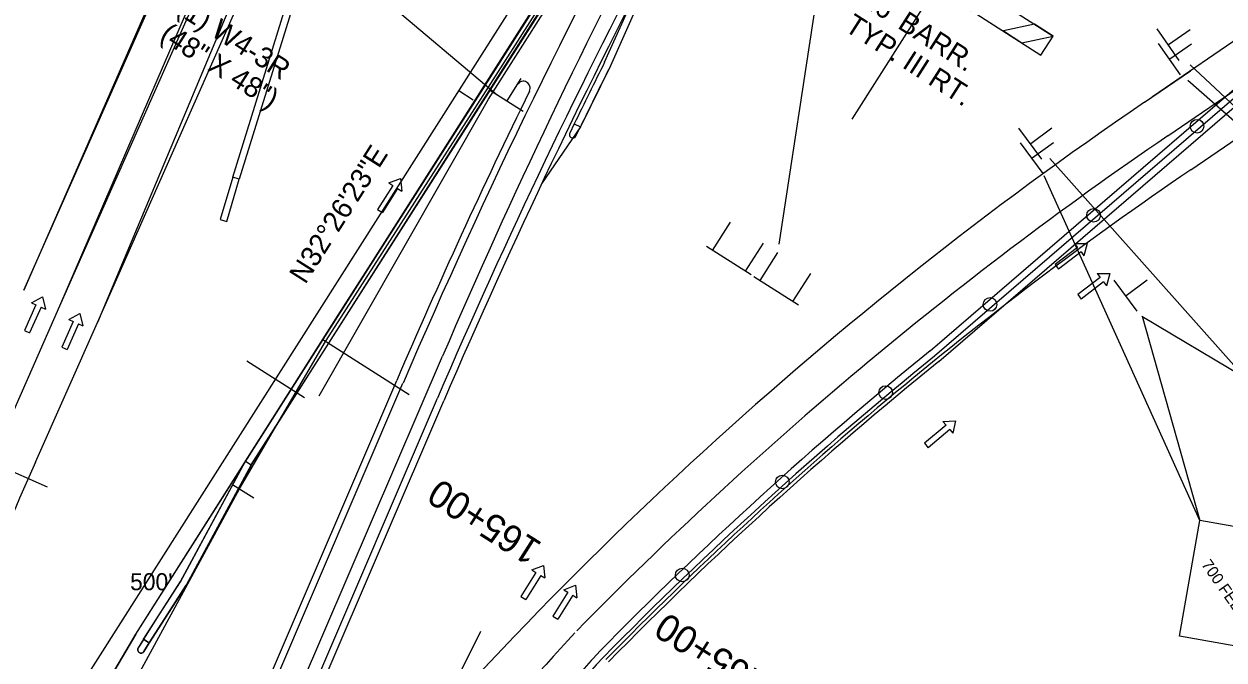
# Model space of a CAD drawing. Extents: x 659657 to 668193, y 633084 to 648639.
# Drawn here: x 661763.9 to 662115.3, y 641469.4 to 641655.6 of the extents above; entities that cross this region are included whole.
import ezdxf

# ---------------------------------------------------------------- set-up
doc = ezdxf.new("R2010")
doc.units = 0
for name, color, linetype in [('R_Draft', 7, 'Continuous'), ('R_MOT_Stage 1A', 7, 'Continuous'), ('R_MOT_Stage 1A_Striping', 7, 'Continuous'), ('R_MOT_Stage 1B', 7, 'Continuous'), ('R_MOT_Stage 1B_Striping', 7, 'Continuous'), ('R_MOT_Stage 1C', 7, 'Continuous'), ('R_MOT_Stage 1C_Striping', 7, 'Continuous'), ('R_MOT_Stage 2', 7, 'Continuous'), ('R_MOT_Stage 2_Striping', 7, 'Continuous'), ('R_MOT_Stage 2_Striping_PPM', 7, 'Continuous'), ('R_MOT_Stage 3_Striping_PPM', 7, 'Continuous'), ('R_MOT_Stage 4_Striping_PPM', 7, 'Continuous'), ('R_MOT_Stage 5_Striping_PPM', 7, 'Continuous'), ('R_ROW Annot', 7, 'Continuous'), ('S_EXISTING_ALIGNMENT', 7, 'Continuous'), ('T_Notes', 7, 'Continuous'), ('T_SIGNAL CONTROL CABINET', 7, 'Continuous'), ('TEMP_SIGNAL_HEAD_STAGE 2', 7, 'Continuous'), ('TEMP_SIGNAL_POLES_STAGE 3', 7, 'Continuous'), ('TEXT_TEMP_SIGNAL_POLES_STAGE 2', 7, 'Continuous')]:
    doc.layers.add(name, color=color, linetype=linetype)

msp = doc.modelspace()

# ---------------------------------------------------------------- linework, layer by layer
at = {"layer": 'R_Draft'}
for p, q in [((662102.51, 641640.73), (662096.07, 641649.95)), ((662099.44, 641645.41), (662105.74, 641649.81)), ((662200.7, 641554.26), (662104.7, 641639.1)), ((662062.3, 641611.81), (662055.63, 641620.87)), ((662059.12, 641616.41), (662065.3, 641620.96)), ((662108.18, 641510.21), (662062.63, 641611.16)), ((662089.81, 641571.52), (662083.14, 641580.58)), ((662086.62, 641576.13), (662092.81, 641580.68)), ((662091.31, 641570.11), (662108.18, 641510.21)), ((662102.25, 641476.33), (662108.18, 641510.21)), ((662142.04, 641504.27), (662108.18, 641510.21)), ((662136.13, 641470.4), (662102.25, 641476.33))]:
    msp.add_line(p, q, dxfattribs=at)
at = {"layer": 'R_MOT_Stage 1A'}
for p, q in [((661809.66, 641492.35), (661828.7, 641527.64)), ((661830.39, 641526.57), (661811.35, 641491.28)), ((661798.88, 641475.5), (661797.27, 641472.97)), ((661798.88, 641475.5), (661800.57, 641474.43)), ((661798.96, 641471.9), (661800.57, 641474.43))]:
    msp.add_line(p, q, dxfattribs=at)
for points in [[(661828.7, 641527.64), (661899.02, 641637.71), (661920.48, 641671.46), (661942.01, 641705.19), (661963.28, 641739.07), (661984.75, 641772.81), (662005.98, 641806.72), (662027.38, 641840.52), (662048.99, 641874.22)], [(661830.39, 641526.57), (661900.71, 641636.63), (661922.17, 641670.39), (661943.7, 641704.12), (661964.97, 641738), (661986.44, 641771.75), (662007.67, 641805.65), (662029.07, 641839.44), (662050.67, 641873.14)], [(661798.88, 641475.5), (661803.42, 641482.62), (661809.66, 641492.35)], [(661800.57, 641474.43), (661805.1, 641481.54), (661811.35, 641491.28)]]:
    msp.add_lwpolyline(points, dxfattribs=at)
msp.add_arc((661798.11, 641472.44), 1, 147.4916, 327.4916, dxfattribs=at)
at = {"layer": 'R_MOT_Stage 1A_Striping'}
for p, q in [((661764.81, 641437.19), (662110.96, 641981.8)), ((661853.01, 641388.39), (661897.69, 641477.85)), ((661771.17, 641433.87), (661796.6, 641476.95))]:
    msp.add_line(p, q, dxfattribs=at)
for points in [[(661796.6, 641476.95), (661855.9, 641570.33), (661877.49, 641604), (661899.02, 641637.71), (661920.48, 641671.46), (661942.01, 641705.19), (661963.28, 641739.07), (661984.75, 641772.81), (662005.98, 641806.72), (662027.38, 641840.52), (662048.99, 641874.22)], [(661895.42, 641633.35), (661891.2, 641636.03)], [(661829.12, 641557), (661845.99, 641546.27)]]:
    msp.add_lwpolyline(points, dxfattribs=at)
at = {"layer": 'R_MOT_Stage 1B'}
for p, q in [((661828.79, 641527.59), (662056.76, 641886.27)), ((661830.47, 641526.51), (662058.45, 641885.2)), ((661933.9, 641644.44), (661942.13, 641662.91)), ((661943.82, 641661.83), (661935.6, 641643.36)), ((661925.01, 641626.4), (661923.69, 641623.7)), ((661925.01, 641626.39), (661926.8, 641625.52)), ((661925.49, 641622.82), (661926.8, 641625.52)), ((661758.57, 641284.51), (661873.02, 641551.2)), ((661772.36, 641278.59), (661886.81, 641545.29)), ((661809.74, 641492.3), (661828.79, 641527.59)), ((661828.7, 641527.64), (661830.39, 641526.57)), ((661830.47, 641526.52), (661811.43, 641491.23)), ((661798.96, 641475.45), (661797.35, 641472.92)), ((661798.96, 641475.45), (661800.65, 641474.37)), ((661799.04, 641471.85), (661800.65, 641474.38))]:
    msp.add_line(p, q, dxfattribs=at)
for points in [[(661943.82, 641661.83), (661935.6, 641643.36), (661926.8, 641625.52), (661915.46, 641608.81)], [(661798.96, 641475.45), (661803.5, 641482.57), (661809.74, 641492.3)], [(661800.65, 641474.38), (661805.19, 641481.49), (661811.43, 641491.23)]]:
    msp.add_lwpolyline(points, dxfattribs=at)
for centre, radius, start, end in [((663629.94, 640797.24), 1896.86, 147.56037, 156.77389), ((663629.94, 640797.24), 1895.86, 153.4571, 154.06509), ((663629.94, 640797.24), 1893.86, 153.46335, 154.07199), ((663629.94, 640797.24), 1911.86, 153.97883, 156.77389), ((661910.08, 641636.86), 2, 333.9788, 147.532), ((661924.59, 641623.26), 1, 153.9653, 333.9653), ((661798.2, 641472.38), 1, 147.4916, 327.4916)]:
    msp.add_arc(centre, radius, start, end, dxfattribs=at)
at = {"layer": 'R_MOT_Stage 1B_Striping'}
for p, q in [((661764.81, 641437.19), (662110.96, 641981.8)), ((661796.6, 641476.95), (662056.76, 641886.27)), ((661760.41, 641283.72), (661874.86, 641550.41)), ((661770.52, 641279.38), (661884.97, 641546.08)), ((661796.6, 641476.95), (661771.17, 641433.87))]:
    msp.add_line(p, q, dxfattribs=at)
for points in [[(661895.42, 641633.35), (661891.2, 641636.03)], [(661829.12, 641557), (661845.99, 641546.27)]]:
    msp.add_lwpolyline(points, dxfattribs=at)
for radius, start in [(1898.86, 147.56037), (1909.86, 151.26731)]:
    msp.add_arc((663629.94, 640797.24), radius, start, 156.77389, dxfattribs=at)
at = {"layer": 'R_MOT_Stage 1C'}
for p, q in [((662029.22, 641559.88), (662143.21, 641658.04)), ((662144.43, 641656.46), (662030.5, 641558.35))]:
    msp.add_line(p, q, dxfattribs=at)
for centre in [(662107.37, 641625.7), (662077.06, 641599.6), (662046.75, 641573.5), (662016.19, 641547.71), (661985.93, 641521.51), (661956.61, 641494.26)]:
    msp.add_circle(centre, 2, dxfattribs=at)
for centre, radius, start, end in [((662748.35, 640671.56), 1142.92, 128.99148, 135.57268), ((662748.35, 640671.56), 1140.92, 128.98995, 135.57268), ((662771.33, 640697.15), 1141.93, 137.30278, 142.29975), ((662771.85, 640696.69), 1140.63, 137.30073, 142.29922)]:
    msp.add_arc(centre, radius, start, end, dxfattribs=at)
at = {"layer": 'R_MOT_Stage 1C_Striping'}
msp.add_line((662031.78, 641556.81), (662145.65, 641654.87), dxfattribs=at)
msp.add_arc((662748.35, 640671.56), 1138.92, 128.98842, 135.57268, dxfattribs=at)
at = {"layer": 'R_MOT_Stage 2'}
for points in [[(661825.01, 641610.82), (661878.63, 641783.81), (661880.54, 641783.21), (661826.92, 641610.23)], [(661825.01, 641610.82), (661821.37, 641598.34), (661823.29, 641597.78), (661826.92, 641610.23)]]:
    msp.add_lwpolyline(points, close=True, dxfattribs=at)
at = {"layer": 'R_MOT_Stage 2_Striping'}
for p, q in [((661803.9, 641669.37), (661763.88, 641577.73)), ((661774.4, 641573.08), (661813.96, 641664.92)), ((661824.02, 641660.47), (661785.37, 641568.22))]:
    msp.add_line(p, q, dxfattribs=at)
at = {"layer": 'R_MOT_Stage 2_Striping_PPM'}
for p, q in [((662474.17, 641893.72), (662094.31, 641634.34)), ((662098.77, 641622.86), (662387.46, 641819.98)), ((662105.54, 641612.95), (662152.42, 641644.96)), ((662092.01, 641632.77), (662105.47, 641641.96)), ((661756.29, 641532.16), (661774.4, 641573.08)), ((661767.26, 641527.3), (661785.37, 641568.22))]:
    msp.add_line(p, q, dxfattribs=at)
for centre, radius, start, end in [((662748.35, 640671.56), 1163.92, 124.32654, 140.57268), ((662748.35, 640671.56), 1151.92, 124.32654, 135.57268), ((662748.35, 640671.56), 1139.92, 124.32654, 135.57268), ((665219.85, 639999.01), 3775.72, 156.12343, 156.82294), ((662771.33, 640697.15), 1150.94, 137.31966, 142.31966)]:
    msp.add_arc(centre, radius, start, end, dxfattribs=at)
at = {"layer": 'R_MOT_Stage 3_Striping_PPM'}
for p, q in [((662474.17, 641893.72), (662094.31, 641634.34)), ((662098.77, 641622.86), (662387.46, 641819.98)), ((661763.88, 641577.73), (661859, 641792.62)), ((661774.4, 641573.08), (661869.52, 641787.96)), ((661785.37, 641568.22), (661880.49, 641783.11)), ((662105.54, 641612.95), (662152.42, 641644.96)), ((662092.01, 641632.77), (662105.47, 641641.96)), ((661756.29, 641532.16), (661774.4, 641573.08)), ((661767.26, 641527.3), (661785.37, 641568.22))]:
    msp.add_line(p, q, dxfattribs=at)
for centre, radius, start, end in [((662748.35, 640671.56), 1163.92, 124.32654, 140.57268), ((662748.35, 640671.56), 1151.92, 124.32654, 135.57268), ((662748.35, 640671.56), 1139.92, 124.32654, 135.57268), ((665219.85, 639999.01), 3775.72, 156.12343, 156.82294), ((662771.33, 640697.15), 1150.94, 137.31966, 142.31966)]:
    msp.add_arc(centre, radius, start, end, dxfattribs=at)
at = {"layer": 'R_MOT_Stage 4_Striping_PPM'}
for p, q in [((662474.17, 641893.72), (662094.31, 641634.34)), ((662098.77, 641622.86), (662387.46, 641819.98)), ((661763.88, 641577.73), (661859, 641792.62)), ((661774.4, 641573.08), (661869.52, 641787.96)), ((661785.37, 641568.22), (661880.49, 641783.11)), ((662105.54, 641612.95), (662152.42, 641644.96)), ((662092.01, 641632.77), (662105.47, 641641.96)), ((661756.29, 641532.16), (661774.4, 641573.08)), ((661767.26, 641527.3), (661785.37, 641568.22))]:
    msp.add_line(p, q, dxfattribs=at)
for centre, radius, start, end in [((662748.35, 640671.56), 1163.92, 124.32654, 140.57268), ((662748.35, 640671.56), 1151.92, 124.32654, 135.57268), ((662748.35, 640671.56), 1139.92, 124.32654, 135.57268), ((665219.85, 639999.01), 3775.72, 156.12343, 156.82294), ((662771.33, 640697.15), 1150.94, 137.31966, 142.31966)]:
    msp.add_arc(centre, radius, start, end, dxfattribs=at)
at = {"layer": 'R_MOT_Stage 5_Striping_PPM'}
for p, q in [((662474.17, 641893.72), (662094.31, 641634.34)), ((662098.77, 641622.86), (662387.46, 641819.98)), ((661763.88, 641577.73), (661859, 641792.62)), ((661774.4, 641573.08), (661869.52, 641787.96)), ((661785.37, 641568.22), (661880.49, 641783.11)), ((662105.54, 641612.95), (662152.42, 641644.96)), ((662092.01, 641632.77), (662105.47, 641641.96)), ((661756.29, 641532.16), (661774.4, 641573.08)), ((661767.26, 641527.3), (661785.37, 641568.22))]:
    msp.add_line(p, q, dxfattribs=at)
for centre, radius, start, end in [((662748.35, 640671.56), 1163.92, 124.32654, 140.57268), ((662748.35, 640671.56), 1151.92, 124.32654, 135.57268), ((662748.35, 640671.56), 1139.92, 124.32654, 135.57268), ((665219.85, 639999.01), 3775.72, 156.12343, 156.82294), ((662771.33, 640697.15), 1150.94, 137.31966, 142.31966)]:
    msp.add_arc(centre, radius, start, end, dxfattribs=at)
at = {"layer": 'R_ROW Annot'}
for p, q in [((662102.09, 641644.95), (662095.65, 641654.17)), ((662099.02, 641649.63), (662105.31, 641654.03)), ((662200.7, 641554.26), (662105.37, 641643.71)), ((662061.88, 641616.02), (662055.21, 641625.08)), ((662058.69, 641620.63), (662064.88, 641625.18)), ((662121.4, 641552.11), (662064.31, 641616.24)), ((662089.81, 641571.52), (662083.14, 641580.58)), ((662086.62, 641576.13), (662092.81, 641580.68)), ((662091.17, 641570.06), (662121.4, 641552.11))]:
    msp.add_line(p, q, dxfattribs=at)
at = {"layer": 'S_EXISTING_ALIGNMENT'}
for p, q in [((661764.81, 641437.19), (662110.96, 641981.8)), ((662006.37, 641627.8), (662163.94, 641875.56)), ((661709.81, 641146.8), (661886.44, 641558.38))]:
    msp.add_line(p, q, dxfattribs=at)
msp.add_arc((663641.52, 640805.21), 1909.86, 147.56037, 156.77389, dxfattribs=at)
at = {"layer": 'T_Notes'}
for p, q in [((662102.09, 641644.95), (662095.65, 641654.17)), ((662099.02, 641649.63), (662105.31, 641654.03)), ((662200.7, 641554.26), (662105.37, 641643.71)), ((662061.88, 641616.02), (662055.21, 641625.08)), ((662058.69, 641620.63), (662064.88, 641625.18)), ((662121.4, 641552.11), (662064.31, 641616.24)), ((662089.81, 641571.52), (662083.14, 641580.58)), ((662086.62, 641576.13), (662092.81, 641580.68)), ((662091.17, 641570.06), (662121.4, 641552.11))]:
    msp.add_line(p, q, dxfattribs=at)
at = {"layer": 'T_SIGNAL CONTROL CABINET'}
for p, q in [((661871.86, 641608.32), (661867.43, 641601.33)), ((661870.67, 641609.07), (661874.14, 641610.34)), ((661870.67, 641609.07), (661871.86, 641608.32)), ((661874.14, 641610.34), (661874.48, 641606.67)), ((661873.29, 641607.42), (661868.86, 641600.43)), ((661873.29, 641607.42), (661874.48, 641606.67)), ((661867.43, 641601.33), (661868.86, 641600.43)), ((662071.52, 641591.34), (662072.38, 641590.22)), ((662071.52, 641591.34), (662075.21, 641591.33)), ((662075.21, 641591.33), (662074.26, 641587.77)), ((662072.38, 641590.22), (662065.81, 641585.19)), ((662073.4, 641588.88), (662066.84, 641583.85)), ((662073.4, 641588.88), (662074.26, 641587.77)), ((662065.81, 641585.19), (662066.84, 641583.85)), ((662079, 641581.44), (662072.43, 641576.4)), ((662080.02, 641580.1), (662073.46, 641575.06)), ((662078.14, 641582.55), (662079, 641581.44)), ((662078.14, 641582.55), (662081.83, 641582.54)), ((662080.02, 641580.1), (662080.88, 641578.98)), ((662081.83, 641582.54), (662080.88, 641578.98)), ((662072.43, 641576.4), (662073.46, 641575.06)), ((661767.33, 641573.41), (661763.98, 641565.84)), ((661768.88, 641572.73), (661765.53, 641565.16)), ((661766.05, 641573.98), (661769.29, 641575.74)), ((661766.05, 641573.98), (661767.33, 641573.41)), ((661768.88, 641572.73), (661770.16, 641572.16)), ((661769.29, 641575.74), (661770.16, 641572.16)), ((661777.01, 641569.1), (661780.25, 641570.86)), ((661780.25, 641570.86), (661781.13, 641567.28)), ((661763.98, 641565.84), (661765.53, 641565.16)), ((661778.3, 641568.54), (661774.95, 641560.97)), ((661779.84, 641567.85), (661776.49, 641560.28)), ((661777.01, 641569.1), (661778.3, 641568.54)), ((661779.84, 641567.85), (661781.13, 641567.28)), ((661826.96, 641519.54), (661852.2, 641562.68)), ((661851.36, 641563.21), (661876.65, 641547.09)), ((661774.95, 641560.97), (661776.49, 641560.28)), ((661724.9, 641540.31), (661770.65, 641520.13)), ((662033.88, 641538.15), (662027.52, 641532.85)), ((662032.98, 641539.23), (662036.66, 641539.37)), ((662032.98, 641539.23), (662033.88, 641538.15)), ((662036.66, 641539.37), (662035.86, 641535.77)), ((662034.96, 641536.85), (662028.6, 641531.55)), ((662034.96, 641536.85), (662035.86, 641535.77)), ((662027.52, 641532.85), (662028.6, 641531.55)), ((661824.9, 641520.75), (661831.22, 641516.89)), ((661791.94, 641455.07), (661826.96, 641519.54)), ((661912.59, 641495.78), (661916.04, 641497.07)), ((661912.59, 641495.78), (661913.79, 641495.03)), ((661916.04, 641497.07), (661916.41, 641493.4)), ((661913.79, 641495.03), (661909.41, 641488.01)), ((661915.22, 641494.14), (661910.85, 641487.12)), ((661915.22, 641494.14), (661916.41, 641493.4)), ((661923.12, 641489.22), (661918.75, 641482.2)), ((661921.93, 641489.96), (661925.38, 641491.26)), ((661921.93, 641489.96), (661923.12, 641489.22)), ((661925.38, 641491.26), (661925.75, 641487.59)), ((661909.41, 641488.01), (661910.85, 641487.12)), ((661924.56, 641488.33), (661920.18, 641481.3)), ((661924.56, 641488.33), (661925.75, 641487.59)), ((661918.75, 641482.2), (661920.18, 641481.3))]:
    msp.add_line(p, q, dxfattribs=at)
for points in [[(661852.2, 641562.68), (661856.74, 641569.79), (661878.33, 641603.47), (661899.87, 641637.17), (661921.33, 641670.93), (661942.85, 641704.66), (661964.13, 641738.53), (661985.6, 641772.28), (662006.82, 641806.18), (662028.23, 641839.98), (662049.83, 641873.68)], [(661850.32, 641546.76), (661899.94, 641633.58), (661978.06, 641756.71)]]:
    msp.add_lwpolyline(points, dxfattribs=at)
at = {"layer": 'TEMP_SIGNAL_HEAD_STAGE 2'}
for p, q in [((661985.03, 641591.15), (661999.17, 641683.82)), ((662020.87, 641680.47), (662065.21, 641652.1)), ((662017.32, 641674.92), (662061.66, 641646.55)), ((662061.66, 641646.55), (662065.21, 641652.1)), ((661965.53, 641589.34), (661970.79, 641597.55)), ((661976.78, 641582.14), (661963.76, 641590.48)), ((661975.14, 641583.2), (661980.39, 641591.41)), ((661979.4, 641580.47), (661984.65, 641588.68)), ((661990.64, 641573.27), (661977.62, 641581.6)), ((661989, 641574.32), (661994.26, 641582.54))]:
    msp.add_line(p, q, dxfattribs=at)
msp.add_lwpolyline([(662065.21, 641652.1), (662059.75, 641655.58), (662050.67, 641653.58), (662056.11, 641650.11)], close=True, dxfattribs=at)
at = {"layer": 'TEMP_SIGNAL_POLES_STAGE 3'}
msp.add_line((661764.81, 641437.19), (662110.96, 641981.8), dxfattribs=at)
for points in [[(661895.42, 641633.35), (661891.2, 641636.03)], [(661829.12, 641557), (661845.99, 641546.27)]]:
    msp.add_lwpolyline(points, dxfattribs=at)
at = {"layer": 'TEXT_TEMP_SIGNAL_POLES_STAGE 2'}
for p, q in [((661869.58, 641662.58), (661902.43, 641634.85)), ((661905.37, 641633.17), (661909.49, 641639.65)), ((661910, 641630.03), (661900.51, 641636.07))]:
    msp.add_line(p, q, dxfattribs=at)

# ---------------------------------------------------------------- texts
at = {"layer": 'R_Draft'}
msp.add_text('700 FEET', height=3.339, rotation=305.0705, dxfattribs=at).set_placement((662108.48, 641497.33))
at = {"layer": 'R_MOT_Stage 1A_Striping'}
for s, height, rotation, p in [('N32%%d26\'23"E', 6, 57.5604, (661846.25, 641579.2)), ('165+00', 8, 147.5604, (661915.96, 641503.47))]:
    msp.add_text(s, height=height, rotation=rotation, dxfattribs=at).set_placement(p)
at = {"layer": 'R_MOT_Stage 1B_Striping'}
for s, height, rotation, p in [('N32%%d26\'23"E', 6, 57.5604, (661846.25, 641579.2)), ('165+00', 8, 147.5604, (661982.43, 641464.3))]:
    msp.add_text(s, height=height, rotation=rotation, dxfattribs=at).set_placement(p)
at = {"layer": 'T_SIGNAL CONTROL CABINET'}
msp.add_text("500'", height=5, dxfattribs=at).set_placement((661794.95, 641489.8))
at = {"layer": 'TEMP_SIGNAL_HEAD_STAGE 2'}
for s, p in [("16' BARR.", (662008.7, 641661.45)), ('TYP. III RT.', (662003.84, 641653.87))]:
    msp.add_text(s, height=6, rotation=327.3866, dxfattribs=at).set_placement(p)
at = {"layer": 'TEMP_SIGNAL_POLES_STAGE 3'}
msp.add_text('N32%%d26\'23"E', height=6, rotation=57.5604, dxfattribs=at).set_placement((661846.25, 641579.2))
at = {"layer": 'TEXT_TEMP_SIGNAL_POLES_STAGE 2'}
for s, p in [('(1) W4-3R', (661808.13, 641658.86)), ('(48" X 48")', (661803.3, 641651.26))]:
    msp.add_text(s, height=6, rotation=327.5579, dxfattribs=at).set_placement(p)

doc.saveas('drawing.dxf')
